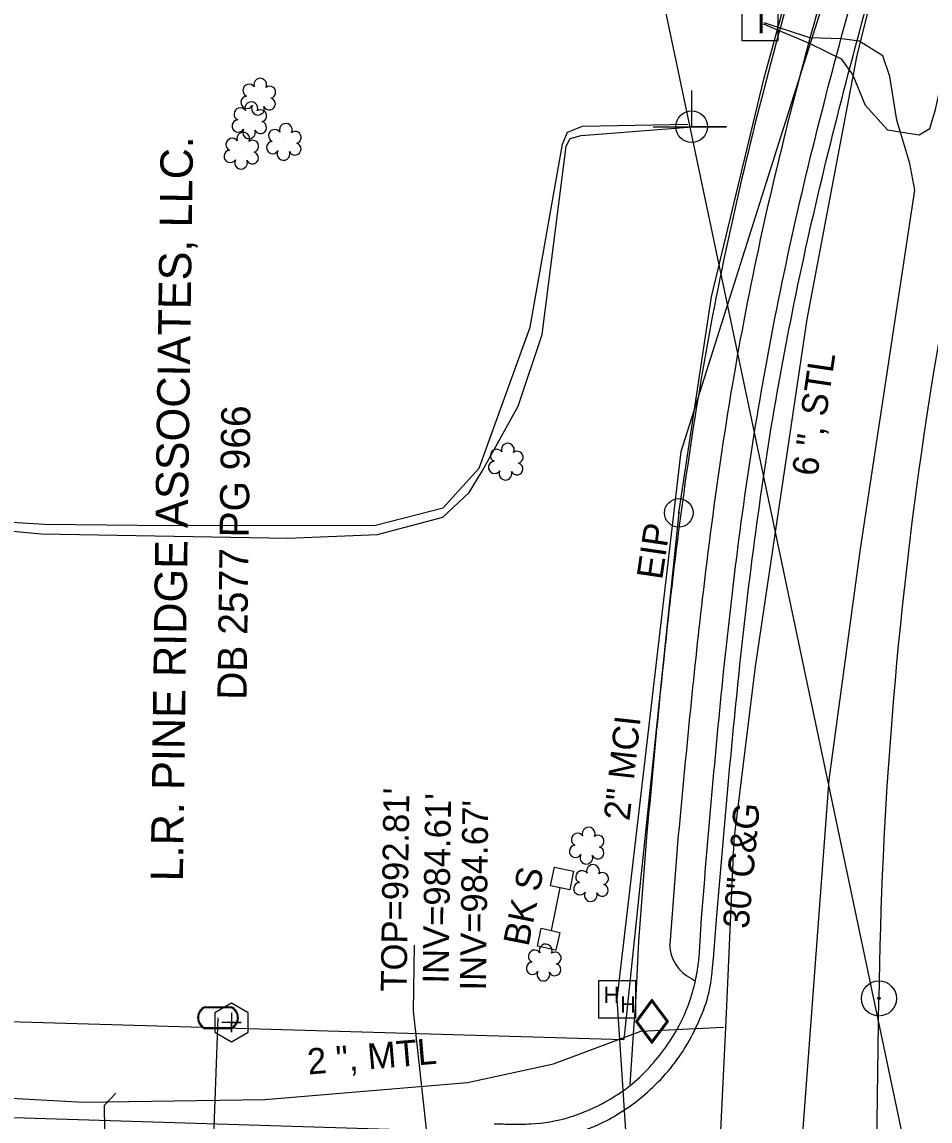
# Model space of a CAD drawing. Extents: x 1614611 to 1617571, y 898867 to 905462.
# Drawn here: x 1615886 to 1616026.4, y 904789.2 to 904959 of the extents above; entities that cross this region are included whole.
import ezdxf

# ---------------------------------------------------------------- set-up
doc = ezdxf.new("R2010")
doc.units = 0
for name, color, linetype in [('Exist Boundary Watershed Residential C 05', 7, 'Continuous'), ('Exist Building', 7, 'Continuous'), ('Exist Building Text', 7, 'Continuous'), ('Exist Drainage Structure Drop Inlet CELL', 7, 'Continuous'), ('Exist Horizontal Alignment Tick Label', 7, 'Continuous'), ('Exist Other Culture Sign', 7, 'Continuous'), ('Exist Plan Preparation Watershed Yellow', 7, 'Continuous'), ('Exist Roads Curbs Text', 7, 'Continuous'), ('Exist Survey Centerline Point CELL', 7, 'Continuous'), ('Exist Utilities Gas UG Line SUE LOS B', 7, 'Continuous'), ('Exist Utilities Gas UG Line SUE LOS B Text', 7, 'Continuous'), ('Exist Utilities Gas Valve CELL', 7, 'Continuous'), ('Exist Utilities Power Joint Use Telephone CELL', 7, 'Continuous'), ('Exist Utilities Sanitary Sewer Manhole Leader', 7, 'Continuous'), ('Exist Utilities Sanitary Sewer Manhole Text', 7, 'Continuous'), ('Exist Utilities Sanitary Sewer UG Line Invert Elevation', 7, 'Continuous'), ('Exist Utilities Telephone Hand Hole CELL', 7, 'Continuous'), ('Exist Utilities Telephone Pedestal CELL', 7, 'Continuous'), ('Exist Utilities Telephone UG Cable SUE LOS B', 7, 'Continuous'), ('Exist Utilities Telephone UG FO SUE LOS C', 7, 'Continuous'), ('Exist Utilities Telephone UG FO SUE LOS C Text', 7, 'Continuous'), ('Exist Utilities TV UG Cable SUE LOS B', 7, 'Continuous'), ('Exist Utilities Water UG Line SUE LOS B', 7, 'Continuous'), ('Exist Vegetation Shrub CELL', 7, 'Continuous'), ('Prop Drainage Structure Catch Basin Grate 840 03E Label', 7, 'Continuous'), ('Prop Drainage Structure Pipe Removal', 7, 'Continuous'), ('Prop Drainage Structure Pipe Removal Label', 7, 'Continuous'), ('Prop Drainage Structure Pipe Stub Out CELL', 7, 'Continuous'), ('Prop Earthen Structure Head Ditch Label', 7, 'Continuous'), ('Prop SS Transition Line', 7, 'Continuous'), ('Raster_Level_2', 7, 'Continuous'), ('Scratch_Level_1', 7, 'Continuous'), ('Scratch_Level_9', 7, 'Continuous')]:
    doc.layers.add(name, color=color, linetype=linetype)

# ---------------------------------------------------------------- blocks, each defined once
blk = doc.blocks.new('EXIST PROPERTY IRON PIN')
at = {"layer": 'Exist Plan Preparation Watershed Yellow'}
for radius in [0.0441, 0.00141]:
    blk.add_circle((0, 0), radius, dxfattribs=at)
blk = doc.blocks.new('EXIST SURVEY CENTERLINE POINT')
at = {"layer": 'Exist Survey Centerline Point CELL'}
for radius in [0.0542, 0.00375]:
    blk.add_circle((0, 0), radius, dxfattribs=at)
blk = doc.blocks.new('EXIST UTILITIES SANITARY SEWER CLEAN-OUT')
at = {"layer": 'Prop Drainage Structure Pipe Stub Out CELL'}
blk.add_line((0, 0), (0, 0), dxfattribs=at)
blk.add_lwpolyline([(-0.0516, 0.0299), (-0.0517, -0.0297), (-0.0001, -0.0596), (0.0516, -0.0299), (0.0517, 0.0297), (0.0001, 0.0596)], close=True, dxfattribs=at)
blk.add_lwpolyline([(0, 0.0302), (0, -0.0302), (0, 0), (0.0302, 0), (-0.0302, 0)], dxfattribs=at)
blk = doc.blocks.new('EXIST UTILITIES TELEPHONE PEDESTAL')
at = {"layer": 'Exist Utilities Telephone Pedestal CELL'}
blk.add_line((0, 0), (0, 0), dxfattribs=at)
blk.add_lwpolyline([(-0.0545, -0.0565), (0.0574, -0.0565), (0.0574, 0.0554), (-0.0545, 0.0554), (-0.0545, -0.0565)], dxfattribs=at)
blk.add_text('T', height=0.0684, dxfattribs=at).set_placement((-0.0226, -0.0343))
blk = doc.blocks.new('EXIST UTILITIES WATER METER')
at = {"layer": 'Prop SS Transition Line'}
blk.add_line((0, 0), (0, 0), dxfattribs=at)
for points in [[(-0.0408, 0.034), (0.0408, 0.034)], [(-0.0408, 0.0312), (0.0408, 0.0312)], [(0.0408, -0.0312), (-0.0413, -0.0312)], [(0.0408, -0.034), (-0.0413, -0.034)]]:
    blk.add_lwpolyline(points, dxfattribs=at)
for centre, radius, start, end in [((-0.0261, -0.0001), 0.0371, 113.178, 245.9794), ((0.0259, 0), 0.0371, 293.6483, 66.3084), ((-0.0259, -0.0001), 0.0347, 115.3009, 243.7824), ((0.0261, 0), 0.0345, 295.1272, 64.8728)]:
    blk.add_arc(centre, radius, start, end, dxfattribs=at)
blk = doc.blocks.new('EXIST UTILITIES GAS VALVE')
at = {"layer": 'Exist Utilities Gas Valve CELL'}
blk.add_line((0, 0), (0, 0), dxfattribs=at)
blk.add_lwpolyline([(0, 0.0683), (-0.0508, 0), (0, -0.0683), (0.0508, 0), (0, 0.0683)], dxfattribs=at)
blk.add_lwpolyline([(0.0458, 0), (0, 0.0615), (-0.0458, 0), (0, -0.0615)], close=True, dxfattribs=at)

msp = doc.modelspace()

# ---------------------------------------------------------------- linework, layer by layer
at = {"layer": 'Exist Boundary Watershed Residential C 05'}
msp.add_line((1615990.73, 904814.39), (1615991.08, 904820.53), dxfattribs=at)
msp.add_lwpolyline([(1615957.87, 904787.39), (1615927.82, 904788.34), (1615886.44, 904789.62), (1615857.19, 904790.51)], dxfattribs=at)
for points in [[(1615991.08, 904820.53), (1615994.5, 904858.52), (1616000.36, 904902.05), (1616010.02, 904946.45), (1616021.47, 904987.52)], [(1615959.03, 904788.72), (1615961.8, 904788.69), (1615964.69, 904788.72), (1615970.55, 904789.71), (1615973.75, 904790.9), (1615979.98, 904794.61), (1615985.56, 904800.59), (1615987.63, 904803.91), (1615990.14, 904810.83), (1615990.44, 904812.39), (1615990.73, 904814.39)]]:
    msp.add_spline(points, degree=3, dxfattribs=at)
at = {"layer": 'Exist Building'}
for points in [[(1615970.71, 904824.91), (1615967.76, 904825.52), (1615968.37, 904828.4), (1615971.31, 904827.78)], [(1615965.71, 904816.18), (1615966.31, 904818.94), (1615969.18, 904818.32), (1615968.58, 904815.56)]]:
    msp.add_lwpolyline(points, close=True, dxfattribs=at)
at = {"layer": 'Exist Other Culture Sign'}
msp.add_lwpolyline([(1615967.9, 904818.6), (1615969.22, 904825.22)], dxfattribs=at)
at = {"layer": 'Exist Utilities Gas UG Line SUE LOS B'}
for points in [[(1616008.07, 904526.35), (1616004.5, 904556.45), (1616000.8, 904594.05), (1615997.92, 904620.35), (1615995.31, 904658.21), (1615994.57, 904671.15), (1615993.49, 904694.5), (1615993.22, 904733.75), (1615992.95, 904745.1), (1615994.07, 904787.68), (1615994.9, 904804.63), (1615996.12, 904832.64), (1615999.45, 904859.38), (1616007.42, 904913.09), (1616015.15, 904953.86), (1616027.47, 905003.13), (1616033.5, 905030.42), (1616046.64, 905085.14), (1616052.58, 905109.27)], [(1615721.3, 904798.85), (1615732.14, 904798.41), (1615763.96, 904797), (1615797.25, 904797.43), (1615833.11, 904798.34), (1615861.95, 904793.95), (1615895.54, 904792.07), (1615923.56, 904792.49), (1615954.89, 904795.14), (1615968.21, 904797.98), (1615981.7, 904803.05), (1615994.47, 904803.67)], [(1615892.94, 904686.04), (1615898.33, 904685.81), (1615897.72, 904721.41), (1615899.19, 904760.41), (1615898.78, 904791.62), (1615900.54, 904793.48)]]:
    msp.add_lwpolyline(points, dxfattribs=at)
at = {"layer": 'Exist Utilities Power Joint Use Telephone CELL'}
msp.add_line((1615989.57, 904942.8), (1615989.57, 904942.8), dxfattribs=at)
msp.add_lwpolyline([(1615983.63, 904942.8), (1615994.97, 904942.77), (1615989.57, 904942.78), (1615989.57, 904948.43)], dxfattribs=at)
msp.add_circle((1615989.57, 904942.81), 2.45, dxfattribs=at)
at = {"layer": 'Exist Utilities Sanitary Sewer Manhole Leader'}
msp.add_lwpolyline([(1615950.78, 904767.79), (1615946.59, 904806.14), (1615946.74, 904816.33)], dxfattribs=at)
at = {"layer": 'Exist Utilities Telephone Hand Hole CELL'}
for p, q in [((1615975.18, 904810.85), (1615975.18, 904805.13)), ((1615980.91, 904810.85), (1615975.18, 904810.85)), ((1615980.91, 904805.13), (1615980.91, 904810.85)), ((1615978.05, 904807.99), (1615978.05, 904807.99)), ((1615975.18, 904805.13), (1615980.91, 904805.13))]:
    msp.add_line(p, q, dxfattribs=at)
at = {"layer": 'Exist Utilities Telephone UG Cable SUE LOS B'}
for points in [[(1616000.59, 904958.72), (1616007.72, 904955.73), (1616012.67, 904953.3), (1616014.46, 904950.79), (1616016.39, 904946.13), (1616019.85, 904942.35), (1616024.71, 904941.54), (1616026.38, 904942.55), (1616027.24, 904945.45), (1616036.99, 904989.37), (1616051.33, 905054.35), (1616059.9, 905091.39), (1616063.65, 905103.92)], [(1616023.33, 904513.19), (1616016.15, 904558.39), (1616009.3, 904603.66), (1616006.62, 904640.17), (1616003.78, 904694.26), (1616004, 904730.49), (1616006.25, 904780.38), (1616010.82, 904841.9), (1616015.64, 904877.58), (1616024.08, 904933.01), (1616023.27, 904937.15), (1616021.29, 904943.82), (1616020.2, 904950.59), (1616019.12, 904953.78), (1616015.47, 904956.02), (1616012.77, 904956.38), (1616007.82, 904956.57), (1616000.75, 904958.85)]]:
    msp.add_lwpolyline(points, dxfattribs=at)
at = {"layer": 'Exist Utilities Telephone UG FO SUE LOS C'}
for p, q in [((1615978.05, 904807.99), (1615987.93, 904892.64)), ((1615992.34, 904593.02), (1615978.05, 904807.99))]:
    msp.add_line(p, q, dxfattribs=at)
msp.add_lwpolyline([(1615987.93, 904892.64), (1616033.7, 905037.04), (1616047.18, 905079.26), (1616058.19, 905113.53)], dxfattribs=at)
at = {"layer": 'Exist Utilities TV UG Cable SUE LOS B'}
msp.add_lwpolyline([(1615856.89, 904884.39), (1615861.74, 904882.4), (1615889.05, 904879.89), (1615927.12, 904879.24), (1615941.01, 904879.82), (1615951.12, 904882.5), (1615955.18, 904886.28), (1615957.2, 904889.59), (1615962.76, 904899.65), (1615966.43, 904910.71), (1615970.16, 904939.8), (1615970.78, 904940.99), (1615972.49, 904941.43), (1615989.04, 904942.74)], dxfattribs=at)
at = {"layer": 'Exist Utilities Water UG Line SUE LOS B'}
msp.add_line((1615915.38, 904778.71), (1615916.35, 904805.13), dxfattribs=at)
at = {"layer": 'Exist Vegetation Shrub CELL'}
for p, q in [((1615922.64, 904947.27), (1615922.64, 904947.27)), ((1615921.27, 904943.62), (1615921.27, 904943.62)), ((1615926.61, 904940.29), (1615926.61, 904940.29)), ((1615920.03, 904938.92), (1615920.03, 904938.92)), ((1615960.91, 904890.86), (1615960.91, 904890.86)), ((1615973.41, 904831.53), (1615973.41, 904831.53)), ((1615974.09, 904825.76), (1615974.09, 904825.76)), ((1615966.77, 904813.48), (1615966.77, 904813.48))]:
    msp.add_line(p, q, dxfattribs=at)
for centre, radius, start, end in [((1615922.87, 904949.31), 0.99, 334.8391, 200.4717), ((1615921.16, 904948.4), 0.968, 35.8908, 245.4216), ((1615924.32, 904948.14), 0.929, 284.4567, 126.0861), ((1615920.84, 904946.57), 0.955, 95.1099, 327.9534), ((1615921.5, 904945.66), 0.99, 334.8391, 200.4717), ((1615924.28, 904946.34), 0.937, 204.9913, 73.4601), ((1615919.79, 904944.75), 0.968, 35.8908, 245.4216), ((1615922.52, 904945.59), 0.984, 151.2797, 21.387), ((1615922.94, 904944.49), 0.929, 284.4567, 126.0861), ((1615919.47, 904942.92), 0.955, 95.1099, 327.9534), ((1615922.91, 904942.69), 0.937, 204.9913, 73.4601), ((1615926.83, 904942.33), 0.99, 334.8391, 200.4717), ((1615920.25, 904940.96), 0.99, 334.8391, 200.4717), ((1615921.14, 904941.94), 0.984, 151.2797, 21.387), ((1615925.12, 904941.42), 0.968, 35.8908, 245.4216), ((1615928.28, 904941.16), 0.929, 284.4567, 126.0861), ((1615918.54, 904940.05), 0.968, 35.8908, 245.4216), ((1615921.7, 904939.79), 0.929, 284.4567, 126.0861), ((1615924.81, 904939.59), 0.955, 95.1099, 327.9534), ((1615928.24, 904939.36), 0.937, 204.9913, 73.4601), ((1615918.23, 904938.22), 0.955, 95.1099, 327.9534), ((1615921.66, 904937.99), 0.937, 204.9913, 73.4601), ((1615926.48, 904938.61), 0.984, 151.2797, 21.387), ((1615919.9, 904937.24), 0.984, 151.2797, 21.387), ((1615961.14, 904892.9), 0.99, 334.8391, 200.4717), ((1615959.43, 904891.99), 0.968, 35.8908, 245.4216), ((1615962.58, 904891.73), 0.929, 284.4567, 126.0861), ((1615959.11, 904890.16), 0.955, 95.1099, 327.9534), ((1615962.55, 904889.93), 0.937, 204.9913, 73.4601), ((1615960.78, 904889.18), 0.984, 151.2797, 21.387), ((1615973.64, 904833.57), 0.99, 334.8391, 200.4717), ((1615971.93, 904832.66), 0.968, 35.8908, 245.4216), ((1615975.08, 904832.4), 0.929, 284.4567, 126.0861), ((1615971.61, 904830.83), 0.955, 95.1099, 327.9534), ((1615975.05, 904830.61), 0.937, 204.9913, 73.4601), ((1615973.28, 904829.85), 0.984, 151.2797, 21.387), ((1615972.61, 904826.88), 0.968, 35.8908, 245.4216), ((1615974.32, 904827.8), 0.99, 334.8391, 200.4717), ((1615975.77, 904826.62), 0.929, 284.4567, 126.0861), ((1615972.29, 904825.05), 0.955, 95.1099, 327.9534), ((1615975.73, 904824.83), 0.937, 204.9913, 73.4601), ((1615973.97, 904824.07), 0.984, 151.2797, 21.387), ((1615965.29, 904814.61), 0.968, 35.8908, 245.4216), ((1615967, 904815.52), 0.99, 334.8391, 200.4717), ((1615968.45, 904814.35), 0.929, 284.4567, 126.0861), ((1615964.97, 904812.77), 0.955, 95.1099, 327.9534), ((1615966.64, 904811.8), 0.984, 151.2797, 21.387), ((1615968.41, 904812.55), 0.937, 204.9913, 73.4601)]:
    msp.add_arc(centre, radius, start, end, dxfattribs=at)
at = {"layer": 'Prop Drainage Structure Catch Basin Grate 840 03E Label'}
msp.add_lwpolyline([(1615852.91, 904883.71), (1615855.33, 904882.28), (1615861.92, 904883.08), (1615889.45, 904881.41), (1615908.74, 904881.21), (1615940.7, 904881.26), (1615951.13, 904883.92), (1615956.73, 904890.04), (1615964.6, 904911.86), (1615969.61, 904940.13), (1615970.36, 904941.99), (1615972.7, 904942.89), (1615988.98, 904943.21)], dxfattribs=at)
at = {"layer": 'Prop Earthen Structure Head Ditch Label'}
for p, q in [((1615887.44, 905426.15), (1616864.55, 900788.06)), ((1616000.74, 904950.16), (1616009.85, 904983.87)), ((1615992.61, 904916.51), (1616000.74, 904950.16)), ((1615987.57, 904883.14), (1615992.61, 904916.51)), ((1615987.57, 904883.14), (1615979.08, 904801.75)), ((1615846.13, 904805.62), (1615979.08, 904801.75))]:
    msp.add_line(p, q, dxfattribs=at)
at = {"layer": 'Raster_Level_2'}
msp.add_line((1616017.4, 904728.08), (1616018.5, 904808.1), dxfattribs=at)
msp.add_arc((1616679.54, 904799.06), 661.11, 164.05, 179.21667, dxfattribs=at)
at = {"layer": 'Scratch_Level_1'}
for p, q in [((1615987.5, 904833.4), (1615986.17, 904816.46)), ((1615989.55, 904811.19), (1615990, 904810.89))]:
    msp.add_line(p, q, dxfattribs=at)
msp.add_lwpolyline([(1615982.65, 904833.7), (1615981.33, 904816.95), (1615980.87, 904807.47), (1615980.62, 904804.13), (1615979.98, 904794.79)], dxfattribs=at)
msp.add_ellipse((1615992.1, 904816.55), major_axis=(-4.03, -4.37), ratio=0.998122, start_param=5.471331, end_param=6.584464, dxfattribs=at)
for points in [[(1616016.89, 905004.54), (1616004.03, 904960.92), (1615993.36, 904916.55), (1615986.31, 904870.27), (1615982.65, 904833.7)], [(1616021.42, 905002.83), (1616008.75, 904959.8), (1615998.16, 904915.65), (1615991.2, 904869.86), (1615987.5, 904833.4)]]:
    msp.add_spline(points, degree=3, dxfattribs=at)
at = {"layer": 'Scratch_Level_9'}
msp.add_line((1615992.93, 904814.25), (1615993.4, 904820.32), dxfattribs=at)
for points in [[(1615993.4, 904820.32), (1615996.89, 904858.32), (1616002.79, 904901.76), (1616012.43, 904945.8), (1616023.78, 904986.91)], [(1615958.82, 904786.16), (1615964.85, 904786.13), (1615975.05, 904788.57), (1615981.45, 904792.55), (1615987.62, 904799.08), (1615989.7, 904802.55), (1615992.52, 904810.45), (1615992.73, 904812.15), (1615992.93, 904814.25)]]:
    msp.add_spline(points, degree=3, dxfattribs=at)

# ---------------------------------------------------------------- block references
at = {"layer": 'Exist Horizontal Alignment Tick Label', "xscale": 50, "yscale": 50, "rotation": 1.7967031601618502e-12}
msp.add_blockref('EXIST SURVEY CENTERLINE POINT', (1616018.5, 904808.1), dxfattribs=at)
at = {"layer": 'Exist Plan Preparation Watershed Yellow', "xscale": 50, "yscale": 50}
msp.add_blockref('EXIST PROPERTY IRON PIN', (1615987.57, 904883.14), dxfattribs=at)
at = {"layer": 'Exist Utilities Gas Valve CELL', "xscale": 50, "yscale": 50}
msp.add_blockref('EXIST UTILITIES GAS VALVE', (1615983.42, 904804.56), dxfattribs=at)
at = {"layer": 'Exist Utilities Telephone Pedestal CELL', "xscale": 50, "yscale": 50}
msp.add_blockref('EXIST UTILITIES TELEPHONE PEDESTAL', (1616000.04, 904958.95), dxfattribs=at)
at = {"layer": 'Prop Drainage Structure Pipe Stub Out CELL', "xscale": 50, "yscale": 50}
msp.add_blockref('EXIST UTILITIES SANITARY SEWER CLEAN-OUT', (1615918.43, 904804.39), dxfattribs=at)
at = {"layer": 'Prop SS Transition Line', "xscale": 50, "yscale": 50}
msp.add_blockref('EXIST UTILITIES WATER METER', (1615916.35, 904805.13), dxfattribs=at)

# ---------------------------------------------------------------- texts
at = {"layer": 'Exist Building Text'}
msp.add_text('BK S', height=4, rotation=78.7696, dxfattribs=at).set_placement((1615964.33, 904816))
at = {"layer": 'Exist Drainage Structure Drop Inlet CELL'}
msp.add_text('EIP', height=4, rotation=81.6333, dxfattribs=at).set_placement((1615985, 904872.7))
at = {"layer": 'Exist Roads Curbs Text'}
msp.add_text('30"C&G', height=4, rotation=84.8526, dxfattribs=at).set_placement((1615998.36, 904818.8))
at = {"layer": 'Exist Utilities Gas UG Line SUE LOS B Text'}
for s, rotation, p in [('6 ", STL', 81.5631, (1616008.98, 904888.67)), ('2 ", MTL', 4.8299, (1615930.31, 904796.34))]:
    msp.add_text(s, height=4, rotation=rotation, dxfattribs=at).set_placement(p)
at = {"layer": 'Exist Utilities Sanitary Sewer Manhole Text'}
msp.add_text("TOP=992.81'", height=4, rotation=89.2167, dxfattribs=at).set_placement((1615945.5, 904809.13))
at = {"layer": 'Exist Utilities Sanitary Sewer UG Line Invert Elevation'}
for s, p in [("INV=984.61'", (1615951.98, 904810.37)), ("INV=984.67'", (1615957.74, 904809.3))]:
    msp.add_text(s, height=4, rotation=89.2167, dxfattribs=at).set_placement(p)
at = {"layer": 'Exist Utilities Telephone Hand Hole CELL'}
for p in [(1615975.96, 904807.4), (1615978.53, 904805.93)]:
    msp.add_text('H', height=2.5, dxfattribs=at).set_placement(p)
at = {"layer": 'Exist Utilities Telephone UG FO SUE LOS C Text'}
msp.add_text('2" MCI', height=4, rotation=83.7617, dxfattribs=at).set_placement((1615979.94, 904835.46))
at = {"layer": 'Prop Drainage Structure Pipe Removal'}
msp.add_text('L.R. PINE RIDGE ASSOCIATES, LLC.', height=5, rotation=89.2167, dxfattribs=at).set_placement((1615910.92, 904826.16))
at = {"layer": 'Prop Drainage Structure Pipe Removal Label'}
msp.add_text('DB 2577 PG 966', height=4.5, rotation=89.2167, dxfattribs=at).set_placement((1615920.74, 904854.23))

doc.saveas('drawing.dxf')
